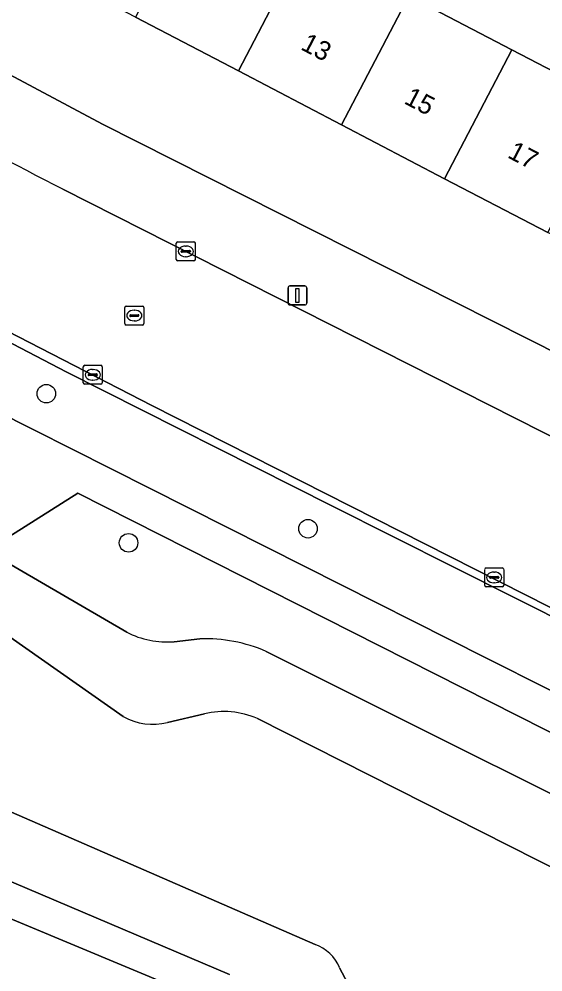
# Model space of a CAD drawing. Extents: x 162803 to 163818, y 381639 to 382475.
# Drawn here: x 163056.5 to 163084.1, y 382007.2 to 382057.4 of the extents above; entities that cross this region are included whole.
import ezdxf

# ---------------------------------------------------------------- set-up
doc = ezdxf.new("R2010")
doc.units = 0
for name, color, linetype in [('IMGEO_Boom', 7, 'Continuous'), ('IMGEO_Erf', 7, 'Continuous'), ('IMGEO_Groenvoorziening', 7, 'Continuous'), ('IMGEO_Kolk', 7, 'Continuous'), ('IMGEO_Lichtmast', 7, 'Continuous'), ('IMGEO_Meer_plas_ven_vijver', 7, 'Continuous'), ('IMGEO_Oever', 7, 'Continuous'), ('IMGEO_Pand', 7, 'Continuous'), ('IMGEO_Pand_nummerreeks', 7, 'Continuous'), ('IMGEO_Rijbaan_lokaal_gesloten', 7, 'Continuous'), ('IMGEO_Rioolput', 7, 'Continuous'), ('IMGEO_Voetpad_gesloten', 7, 'Continuous'), ('IMGEO_Voetpad_open', 7, 'Continuous')]:
    doc.layers.add(name, color=color, linetype=linetype)

msp = doc.modelspace()

# ---------------------------------------------------------------- linework, layer by layer
at = {"layer": 'IMGEO_Boom'}
for centre in [(163057.946, 382037.694), (163071.725, 382030.584), (163062.275, 382029.84)]:
    msp.add_circle(centre, 0.489, dxfattribs=at)
at = {"layer": 'IMGEO_Erf'}
msp.add_lwpolyline([(163033.931, 382069.45), (163032.699, 382067.446), (163044.08, 382060.873), (163060.9, 382051.896), (163109.381, 382027.414), (163111.619, 382031.924), (163106.058, 382034.831), (163100.632, 382037.667), (163095.203, 382040.505), (163089.777, 382043.341), (163084.349, 382046.178), (163078.921, 382049.015), (163073.494, 382051.852), (163068.067, 382054.689), (163062.64, 382057.526), (163057.213, 382060.363), (163051.786, 382063.199), (163046.358, 382066.036), (163040.931, 382068.873), (163035.364, 382071.783)], close=True, dxfattribs=at)
msp.add_lwpolyline([(163077.029, 382058.639), (163082.461, 382055.81), (163087.892, 382052.981)], dxfattribs=at)
at = {"layer": 'IMGEO_Groenvoorziening'}
msp.add_lwpolyline([(163058.984, 382038.838), (163046.569, 382045.324), (163044.701, 382042.138), (163045.023, 382041.967), (163071.552, 382028.597), (163081.096, 382023.789), (163087.66, 382020.483), (163091.938, 382018.328), (163093.518, 382021.402), (163092.199, 382022.031), (163089.255, 382023.601), (163082.613, 382026.944), (163072.977, 382031.794)], close=True, dxfattribs=at)
for points in [[(163044.261, 382036.16), (163048.875, 382033.469), (163055.32, 382029.128), (163062.177, 382025.132)], [(163120.307, 381990.014), (163122.661, 381989.11), (163126.47, 381998.601), (163094.326, 382014.878), (163059.605, 382032.46), (163055.971, 382030.152)], [(163064.672, 382024.632), (163066.032, 382024.779)], [(163069.528, 382024.117), (163093.627, 382012.072)], [(163067.583, 382007.102), (163030.824, 382022.727), (163030.686, 382020.628), (163064.744, 382006.417)]]:
    msp.add_lwpolyline(points, dxfattribs=at)
for centre, radius, start, end in [((163064.324, 382029.372), 4.753, 243.1404, 274.1956), ((163066.353, 382016.91), 7.875, 66.2216, 92.3334)]:
    msp.add_arc(centre, radius, start, end, dxfattribs=at)
at = {"layer": 'IMGEO_Kolk'}
for p, q in [((163064.79, 382044.764), (163064.79, 382045.616)), ((163064.865, 382045.69), (163065.717, 382045.69)), ((163065.278, 382045.47), (163065.303, 382045.47)), ((163065.791, 382045.616), (163065.791, 382044.764)), ((163065.049, 382045.184), (163065.049, 382045.196)), ((163065.487, 382045.147), (163065.089, 382045.147)), ((163065.092, 382045.233), (163065.49, 382045.233)), ((163065.301, 382044.91), (163065.276, 382044.91)), ((163065.533, 382045.196), (163065.533, 382045.184)), ((163065.717, 382044.69), (163064.865, 382044.69)), ((163059.89, 382038.264), (163059.89, 382039.116)), ((163059.965, 382039.19), (163060.817, 382039.19)), ((163060.378, 382038.97), (163060.403, 382038.97)), ((163060.891, 382039.116), (163060.891, 382038.264)), ((163060.149, 382038.684), (163060.149, 382038.696)), ((163060.587, 382038.647), (163060.189, 382038.647)), ((163060.192, 382038.733), (163060.59, 382038.733)), ((163060.401, 382038.41), (163060.376, 382038.41)), ((163060.633, 382038.696), (163060.633, 382038.684)), ((163060.817, 382038.19), (163059.965, 382038.19)), ((163081.029, 382027.593), (163081.029, 382028.445)), ((163081.104, 382028.519), (163081.956, 382028.519)), ((163081.517, 382028.299), (163081.542, 382028.299)), ((163082.03, 382028.445), (163082.03, 382027.593)), ((163081.288, 382028.013), (163081.288, 382028.025)), ((163081.726, 382027.976), (163081.328, 382027.976)), ((163081.331, 382028.062), (163081.729, 382028.062)), ((163081.772, 382028.025), (163081.772, 382028.013)), ((163081.956, 382027.519), (163081.104, 382027.519)), ((163081.54, 382027.739), (163081.515, 382027.739))]:
    msp.add_line(p, q, dxfattribs=at)
for points in [[(163064.79, 382044.764), (163064.79, 382045.616)], [(163064.865, 382045.69), (163065.717, 382045.69)], [(163065.791, 382045.616), (163065.791, 382044.764)], [(163065.717, 382044.69), (163064.865, 382044.69)], [(163059.89, 382038.264), (163059.89, 382039.116)], [(163059.965, 382039.19), (163060.817, 382039.19)], [(163060.891, 382039.116), (163060.891, 382038.264)], [(163060.817, 382038.19), (163059.965, 382038.19)], [(163081.029, 382027.593), (163081.029, 382028.445)], [(163081.104, 382028.519), (163081.956, 382028.519)], [(163082.03, 382028.445), (163082.03, 382027.593)], [(163081.956, 382027.519), (163081.104, 382027.519)]]:
    msp.add_lwpolyline(points, dxfattribs=at)
for centre, radius, start, end in [((163064.867, 382045.614), 0.0765, 91.552, 178.448), ((163064.867, 382045.614), 0.0765, 91.552, 178.448), ((163065.715, 382045.614), 0.0765, 1.552, 88.448), ((163065.715, 382045.614), 0.0765, 1.552, 88.448), ((163065.089, 382045.193), 0.0403, 85.8775, 175.7526), ((163065.086, 382045.183), 0.0366, 178.938, 274.7102), ((163065.49, 382045.19), 0.043, 264.8664, 352.4533), ((163065.494, 382045.195), 0.0386, 1.7309, 96.639), ((163064.867, 382044.766), 0.0765, 181.552, 268.448), ((163064.867, 382044.766), 0.0765, 181.552, 268.448), ((163065.715, 382044.766), 0.0765, 271.552, 358.448), ((163065.715, 382044.766), 0.0765, 271.552, 358.448), ((163059.967, 382039.114), 0.0765, 91.552, 178.448), ((163059.967, 382039.114), 0.0765, 91.552, 178.448), ((163060.815, 382039.114), 0.0765, 1.552, 88.448), ((163060.815, 382039.114), 0.0765, 1.552, 88.448), ((163060.189, 382038.693), 0.0403, 85.8775, 175.7526), ((163060.186, 382038.683), 0.0366, 178.938, 274.7102), ((163060.59, 382038.69), 0.043, 264.8664, 352.4533), ((163060.594, 382038.695), 0.0386, 1.7309, 96.639), ((163059.967, 382038.266), 0.0765, 181.552, 268.448), ((163059.967, 382038.266), 0.0765, 181.552, 268.448), ((163060.815, 382038.266), 0.0765, 271.552, 358.448), ((163060.815, 382038.266), 0.0765, 271.552, 358.448), ((163081.106, 382028.443), 0.0765, 91.552, 178.448), ((163081.106, 382028.443), 0.0765, 91.552, 178.448), ((163081.954, 382028.443), 0.0765, 1.552, 88.448), ((163081.954, 382028.443), 0.0765, 1.552, 88.448), ((163081.328, 382028.022), 0.0403, 85.8775, 175.7526), ((163081.325, 382028.012), 0.0366, 178.938, 274.7102), ((163081.729, 382028.019), 0.043, 264.8664, 352.4533), ((163081.733, 382028.024), 0.0386, 1.7309, 96.639), ((163081.106, 382027.595), 0.0765, 181.552, 268.448), ((163081.106, 382027.595), 0.0765, 181.552, 268.448), ((163081.954, 382027.595), 0.0765, 271.552, 358.448), ((163081.954, 382027.595), 0.0765, 271.552, 358.448)]:
    msp.add_arc(centre, radius, start, end, dxfattribs=at)
for centre, major_axis, ratio, start_param, end_param in [((163065.277, 382045.19), (-0.387, 0.002), 0.722429, 4.712389, 7.853982), ((163065.302, 382045.19), (-0.39, 0.002), 0.717154, 1.570796, 4.712389), ((163060.377, 382038.69), (-0.387, 0.002), 0.722429, 4.712389, 7.853982), ((163060.402, 382038.69), (-0.39, 0.002), 0.717154, 1.570796, 4.712389), ((163081.516, 382028.019), (-0.387, 0.002), 0.722429, 4.712389, 7.853982), ((163081.541, 382028.019), (-0.39, 0.002), 0.717154, 1.570796, 4.712389)]:
    msp.add_ellipse(centre, major_axis=major_axis, ratio=ratio, start_param=start_param, end_param=end_param, dxfattribs=at)
at = {"layer": 'IMGEO_Lichtmast'}
for p, q in [((163070.771, 382043.366), (163071.561, 382043.366)), ((163071.561, 382043.366), (163070.771, 382043.366)), ((163070.671, 382042.466), (163070.671, 382043.266)), ((163070.671, 382043.266), (163070.671, 382042.466)), ((163071.661, 382043.266), (163071.661, 382042.466)), ((163071.661, 382042.466), (163071.661, 382043.266)), ((163071.561, 382042.366), (163070.771, 382042.366)), ((163070.771, 382042.366), (163071.561, 382042.366))]:
    msp.add_line(p, q, dxfattribs=at)
msp.add_lwpolyline([(163071.091, 382043.241), (163071.241, 382043.241), (163071.241, 382042.491), (163071.091, 382042.491), (163071.091, 382043.241)], dxfattribs=at)
for centre, start, end in [((163070.771, 382043.266), 90, 180), ((163070.771, 382043.266), 90, 180), ((163071.561, 382043.266), 0, 90), ((163071.561, 382043.266), 360, 90), ((163070.771, 382042.466), 180, 270), ((163070.771, 382042.466), 180, 270), ((163071.561, 382042.466), 270, 0), ((163071.561, 382042.466), 270, 0)]:
    msp.add_arc(centre, 0.1, start, end, dxfattribs=at)
at = {"layer": 'IMGEO_Meer_plas_ven_vijver'}
for points in [[(163061.997, 382020.698), (163043.303, 382033.81)], [(163021.58, 382030.689), (163031.075, 382026.555), (163072.1, 382008.691)], [(163066.268, 382020.842), (163064.325, 382020.386)], [(163092.613, 382008.674), (163069.063, 382020.588)], [(163073.387, 382007.468), (163083.459, 381988.495)]]:
    msp.add_lwpolyline(points, dxfattribs=at)
for centre, radius, start, end in [((163067.278, 382016.448), 4.509, 66.6731, 102.9417), ((163063.535, 382023.333), 3.051, 239.7307, 285.0026), ((163071.343, 382006.606), 2.219, 22.8759, 70.0453)]:
    msp.add_arc(centre, radius, start, end, dxfattribs=at)
at = {"layer": 'IMGEO_Oever'}
for points in [[(163062.177, 382025.132), (163055.32, 382029.128), (163048.875, 382033.469), (163044.261, 382036.16)], [(163043.303, 382033.81), (163061.997, 382020.698)], [(163072.1, 382008.691), (163031.075, 382026.555), (163030.824, 382022.727), (163067.583, 382007.102)], [(163066.032, 382024.779), (163064.672, 382024.632)], [(163093.627, 382012.072), (163069.528, 382024.117)], [(163064.325, 382020.386), (163066.268, 382020.842)], [(163069.063, 382020.588), (163092.613, 382008.674)], [(163083.459, 381988.495), (163073.387, 382007.468)]]:
    msp.add_lwpolyline(points, dxfattribs=at)
for centre, radius, start, end in [((163064.324, 382029.372), 4.753, 243.1404, 274.1956), ((163066.353, 382016.91), 7.875, 66.2216, 92.3334), ((163067.278, 382016.448), 4.509, 66.6731, 102.9417), ((163063.535, 382023.333), 3.051, 239.7307, 285.0026), ((163071.343, 382006.606), 2.219, 22.8759, 70.0453)]:
    msp.add_arc(centre, radius, start, end, dxfattribs=at)
at = {"layer": 'IMGEO_Pand'}
for points in [[(163068.067, 382054.689), (163071.598, 382061.467), (163066.165, 382064.296), (163062.64, 382057.526)], [(163068.067, 382054.689), (163073.494, 382051.852), (163077.029, 382058.639), (163071.598, 382061.467)], [(163082.461, 382055.81), (163077.029, 382058.639), (163073.494, 382051.852), (163078.921, 382049.015)], [(163087.892, 382052.981), (163082.461, 382055.81), (163078.921, 382049.015), (163084.349, 382046.178)]]:
    msp.add_lwpolyline(points, close=True, dxfattribs=at)
at = {"layer": 'IMGEO_Rijbaan_lokaal_gesloten'}
for points in [[(163028.918, 382055.659), (163034.955, 382052.168), (163050.014, 382044.011), (163063.5, 382037.077), (163108.02, 382014.523), (163116.873, 382009.768), (163125.34, 382004.935), (163128.383, 382010.14), (163126.251, 382011.386), (163125.038, 382012.095)], [(163124.04, 382013.268), (163123.601, 382014.833), (163123.144, 382015.469), (163113.017, 382021.144), (163112.302, 382021.503), (163107.612, 382023.857), (163085.471, 382034.97), (163058.822, 382048.466)]]:
    msp.add_lwpolyline(points, dxfattribs=at)
msp.add_arc((163381.214, 382674.305), 703.996, 241.336179, 242.745419, dxfattribs=at)
at = {"layer": 'IMGEO_Rioolput'}
for p, q in [((163062.154, 382042.31), (163063.006, 382042.31)), ((163062.079, 382041.384), (163062.079, 382042.236)), ((163062.338, 382041.804), (163062.338, 382041.816)), ((163062.381, 382041.853), (163062.779, 382041.853)), ((163062.567, 382042.09), (163062.592, 382042.09)), ((163062.822, 382041.816), (163062.822, 382041.804)), ((163063.08, 382042.236), (163063.08, 382041.384)), ((163063.006, 382041.31), (163062.154, 382041.31)), ((163062.776, 382041.767), (163062.378, 382041.767)), ((163062.59, 382041.53), (163062.565, 382041.53))]:
    msp.add_line(p, q, dxfattribs=at)
for points in [[(163062.154, 382042.31), (163063.006, 382042.31)], [(163062.079, 382041.384), (163062.079, 382042.236)], [(163063.08, 382042.236), (163063.08, 382041.384)], [(163063.006, 382041.31), (163062.154, 382041.31)]]:
    msp.add_lwpolyline(points, dxfattribs=at)
for centre, radius, start, end in [((163062.156, 382042.234), 0.0765, 91.552, 178.448), ((163062.156, 382042.234), 0.0765, 91.552, 178.448), ((163063.004, 382042.234), 0.0765, 1.552, 88.448), ((163063.004, 382042.234), 0.0765, 1.552, 88.448), ((163062.378, 382041.813), 0.0403, 85.8775, 175.7526), ((163062.375, 382041.803), 0.0366, 178.938, 274.7102), ((163062.779, 382041.81), 0.043, 264.8664, 352.4533), ((163062.783, 382041.815), 0.0386, 1.7309, 96.639), ((163062.156, 382041.386), 0.0765, 181.552, 268.448), ((163062.156, 382041.386), 0.0765, 181.552, 268.448), ((163063.004, 382041.386), 0.0765, 271.552, 358.448), ((163063.004, 382041.386), 0.0765, 271.552, 358.448)]:
    msp.add_arc(centre, radius, start, end, dxfattribs=at)
for centre, major_axis, ratio, start_param, end_param in [((163062.566, 382041.81), (-0.387, 0.002), 0.722429, 4.712389, 7.853982), ((163062.591, 382041.81), (-0.39, 0.002), 0.717154, 1.570796, 4.712389)]:
    msp.add_ellipse(centre, major_axis=major_axis, ratio=ratio, start_param=start_param, end_param=end_param, dxfattribs=at)
at = {"layer": 'IMGEO_Voetpad_gesloten'}
msp.add_lwpolyline([(163064.744, 382006.417), (163030.686, 382020.628), (163022.151, 382024.19)], dxfattribs=at)
at = {"layer": 'IMGEO_Voetpad_open'}
for points in [[(163000.959, 382073.995), (163003.733, 382071.977), (163014.396, 382064.481), (163016.465, 382062.979), (163021.065, 382059.867), (163029.316, 382054.876), (163031.983, 382053.266), (163046.569, 382045.324), (163058.984, 382038.838), (163072.977, 382031.794), (163082.613, 382026.944), (163089.255, 382023.601)], [(163058.822, 382048.466), (163085.471, 382034.97), (163107.612, 382023.857), (163109.381, 382027.414), (163060.9, 382051.896), (163044.08, 382060.873), (163032.699, 382067.446), (163030.56, 382064.019), (163030.604, 382063.994), (163030.648, 382063.968)], [(163055.971, 382030.152), (163059.605, 382032.46), (163094.326, 382014.878), (163126.47, 381998.601), (163128.77, 381997.436), (163129.487, 381999.207), (163094.602, 382016.947), (163096.2, 382020.075), (163097.298, 382019.509), (163107.979, 382014.063), (163124.845, 382004.567), (163125.34, 382004.935), (163116.873, 382009.768), (163108.02, 382014.523), (163063.5, 382037.077), (163050.014, 382044.011), (163034.955, 382052.168), (163028.918, 382055.659)], [(163087.66, 382020.483), (163081.096, 382023.789), (163071.552, 382028.597), (163045.023, 382041.967)]]:
    msp.add_lwpolyline(points, dxfattribs=at)
msp.add_arc((163381.214, 382674.305), 703.996, 241.336179, 242.745419, dxfattribs=at)

# ---------------------------------------------------------------- texts
at = {"layer": 'IMGEO_Pand_nummerreeks'}
for s, p in [('13', (163071.285, 382055.851)), ('15', (163076.731, 382053.004)), ('17', (163082.178, 382050.157))]:
    msp.add_text(s, height=1, rotation=332.4036, dxfattribs=at).set_placement(p)

doc.saveas('drawing.dxf')
